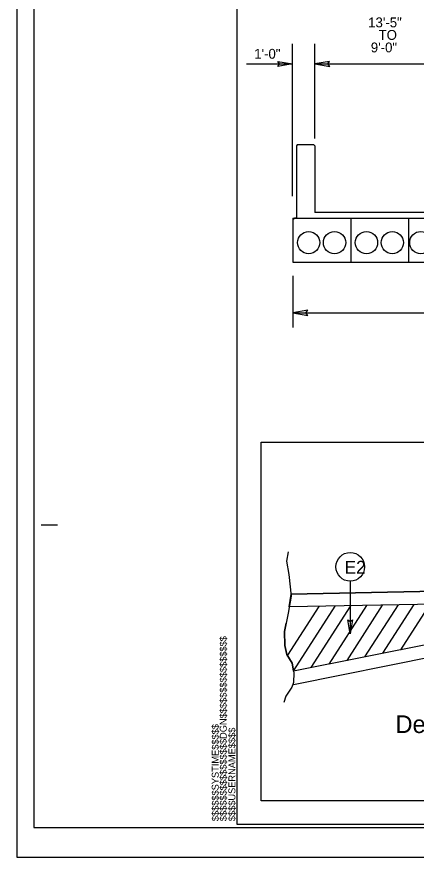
# Model space of a CAD drawing. Extents: x 1818040 to 1825768, y 638918 to 648046.
# Drawn here: x 1820393 to 1820696, y 645383 to 646022 of the extents above; entities that cross this region are included whole.
import ezdxf

# ---------------------------------------------------------------- set-up
doc = ezdxf.new("R2010")
doc.units = 0
for name, color, linetype in [('Default', 7, 'Continuous'), ('Old_Level_1', 7, 'Continuous'), ('Sheet Data Field CELL', 7, 'Continuous'), ('Sheet Plot Border Inside CELL', 7, 'Continuous'), ('Sheet Plot Border Outside CELL', 7, 'Continuous'), ('Sheet Typical CELL', 7, 'Continuous'), ('Typical Bridge Rail CELL', 7, 'Continuous'), ('Typical Detail Wedge2 CELL', 7, 'Continuous'), ('Typical ID Circle CELL', 7, 'Continuous'), ('Typical Terminator CELL', 7, 'Continuous'), ('Typical Text General CELL', 7, 'Continuous'), ('Typical Text ID Circle CELL', 7, 'Continuous')]:
    doc.layers.add(name, color=color, linetype=linetype)

msp = doc.modelspace()

# ---------------------------------------------------------------- linework, layer by layer
at = {"layer": 'Default'}
for p, q in [((1820602.34, 645885.64), (1820602.34, 646001.32)), ((1820619.19, 645929.41), (1820619.19, 646001.32)), ((1820567.26, 645986.11), (1820602.34, 645986.11)), ((1820619.19, 645986.11), (1820714.57, 645986.11)), ((1820602.6, 645869), (1821170.98, 645869)), ((1820602.6, 645869), (1820602.6, 645835.41)), ((1820862.17, 645873.14), (1820619.19, 645873.14)), ((1820646.5, 645869), (1820646.5, 645835.41)), ((1820646.5, 645869), (1820646.5, 645835.41)), ((1820690.4, 645869), (1820690.4, 645835.41)), ((1820602.6, 645835.41), (1821170.98, 645835.41)), ((1820602.56, 645825.17), (1820602.56, 645785.89)), ((1820602.56, 645796.99), (1821170.98, 645796.99))]:
    msp.add_line(p, q, dxfattribs=at)
for centre in [(1820614.52, 645850.35), (1820634.15, 645850.35), (1820658.42, 645850.35), (1820678.05, 645850.35), (1820699.72, 645850.36)]:
    msp.add_circle(centre, 8.47, dxfattribs=at)
at = {"layer": 'Old_Level_1'}
msp.add_lwpolyline([(1820578.56, 645698.83), (1821137.94, 645698.83), (1821137.94, 645426.3), (1820578.56, 645426.3)], close=True, dxfattribs=at)
at = {"layer": 'Sheet Plot Border Inside CELL'}
msp.add_lwpolyline([(1822072.43, 646461.05), (1820405.93, 646461.05), (1820405.93, 645405.95), (1822072.43, 645405.95)], close=True, dxfattribs=at)
at = {"layer": 'Sheet Plot Border Outside CELL'}
msp.add_lwpolyline([(1822076.93, 646483.5), (1820392.93, 646483.5), (1820392.93, 645383.5), (1822076.93, 645383.5)], close=True, dxfattribs=at)
at = {"layer": 'Sheet Typical CELL'}
for p, q in [((1820392.93, 646483.5), (1820392.93, 645383.5)), ((1820411.43, 645636), (1820423.93, 645636)), ((1820559.93, 645408.5), (1820559.93, 645408.5)), ((1820559.93, 645408.5), (1820559.93, 645408.5)), ((1820559.93, 645408.5), (1820559.93, 645408.5)), ((1820559.93, 645408.5), (1820559.93, 645408.5)), ((1820559.93, 645408.5), (1820559.93, 645408.5)), ((1820559.93, 645408.5), (1820559.93, 645408.5)), ((1820392.93, 645383.5), (1822076.93, 645383.5))]:
    msp.add_line(p, q, dxfattribs=at)
msp.add_lwpolyline([(1822059.93, 646458.5), (1820559.93, 646458.5), (1820559.93, 645408.5), (1822059.93, 645408.5)], close=True, dxfattribs=at)
msp.add_lwpolyline([(1820597.43, 645408.5), (1820597.43, 645408.5)], dxfattribs=at)
at = {"layer": 'Typical Bridge Rail CELL'}
for p, q in [((1820605.86, 645924.62), (1820605.2, 645923.96)), ((1820605.2, 645923.96), (1820605.2, 645869)), ((1820618.46, 645924.62), (1820605.86, 645924.62)), ((1820619.19, 645923.89), (1820618.46, 645924.62)), ((1820619.19, 645923.89), (1820619.19, 645873.14)), ((1820603.9, 645869), (1820602.6, 645867.69)), ((1820605.2, 645869), (1820603.9, 645869)), ((1820602.6, 645867.69), (1820602.6, 645858.57))]:
    msp.add_line(p, q, dxfattribs=at)
at = {"layer": 'Typical Detail Wedge2 CELL'}
for p, q in [((1820598.9, 645615.52), (1820597.61, 645608.39)), ((1820597.61, 645608.39), (1820599.56, 645598.25)), ((1820599.56, 645598.25), (1820601.28, 645581.83)), ((1820844.66, 645588.25), (1820601.17, 645583.39)), ((1820601.17, 645583.39), (1820844.66, 645588.25)), ((1820601.28, 645581.83), (1820598.9, 645568.87)), ((1820599.78, 645573.6), (1820601.17, 645583.39)), ((1820823.31, 645578.07), (1820599.78, 645573.6)), ((1820823.31, 645578.07), (1820599.78, 645573.6)), ((1820634.27, 645574.29), (1820602.91, 645525.33)), ((1820646.3, 645574.53), (1820616.17, 645527.5)), ((1820658.33, 645574.77), (1820629.79, 645530.22)), ((1820670.36, 645575.01), (1820643.41, 645532.95)), ((1820682.39, 645575.25), (1820657.03, 645535.67)), ((1820694.42, 645575.5), (1820670.66, 645538.4)), ((1820706.45, 645575.74), (1820684.28, 645541.12)), ((1820598.9, 645568.87), (1820596.1, 645554.83)), ((1820622.24, 645574.05), (1820598.43, 645536.89)), ((1820845.03, 645573.28), (1820603, 645524.86)), ((1820844.58, 645562.86), (1820602.92, 645514.52)), ((1820596.1, 645554.83), (1820596.32, 645544.24)), ((1820596.32, 645544.24), (1820598.05, 645537.56)), ((1820598.05, 645537.56), (1820601.94, 645530.85)), ((1820601.94, 645530.85), (1820603.23, 645523.51)), ((1820603.23, 645523.51), (1820603.01, 645516.17)), ((1820601.72, 645512.71), (1820597.19, 645505.79)), ((1820603.01, 645516.17), (1820601.72, 645512.71)), ((1820597.19, 645505.79), (1820595.67, 645501.04))]:
    msp.add_line(p, q, dxfattribs=at)
msp.add_lwpolyline([(1820602.99, 645524.86), (1820601.94, 645530.85), (1820598.05, 645537.56), (1820596.32, 645544.24), (1820596.1, 645554.83), (1820597.4, 645561.34)], dxfattribs=at)
at = {"layer": 'Typical ID Circle CELL'}
msp.add_line((1820646.1, 645593.17), (1820646.1, 645553.2), dxfattribs=at)
msp.add_circle((1820646.09, 645604.05), 10.88, dxfattribs=at)
at = {"layer": 'Typical Terminator CELL'}
for points in [[(1820591.09, 645988.05), (1820602.34, 645986.11), (1820591.03, 645984.11), (1820592.46, 645986.11)], [(1820630.44, 645988.05), (1820619.19, 645986.11), (1820630.5, 645984.11), (1820629.06, 645986.11)], [(1820613.81, 645798.93), (1820602.56, 645796.99), (1820613.87, 645794.99), (1820612.44, 645796.99)], [(1820647.91, 645563.75), (1820646.1, 645553.2), (1820644.22, 645563.81), (1820646.1, 645562.46)], [(1820647.91, 645563.75), (1820646.1, 645553.2), (1820644.22, 645563.81), (1820646.1, 645562.46)]]:
    msp.add_lwpolyline(points, close=True, dxfattribs=at)

# ---------------------------------------------------------------- texts
at = {"layer": 'Sheet Data Field CELL'}
for s, p in [('13\'-5" ', (1820659.69, 646013.87)), ('TO ', (1820667.61, 646004.37)), ('9\'-0"', (1820661.7, 645994.86)), ('1\'-0"', (1820573.16, 645990.05))]:
    msp.add_text(s, height=7.5, dxfattribs=at).set_placement(p)
at = {"layer": 'Sheet Typical CELL'}
for s, p in [('$$$$$$$$$$$$$$$$DGN$$$$$$$$$$$$$$$$', (1820552.28, 645410.86)), ('$$$$$$SYSTIME$$$$$', (1820546.23, 645410.86)), ('$$$$USERNAME$$$$', (1820558.86, 645410.87))]:
    msp.add_text(s, height=5.25, rotation=90, dxfattribs=at).set_placement(p)
at = {"layer": 'Typical Text General CELL'}
msp.add_text('Detail Showing Method of Wedging', height=13.4275, dxfattribs=at).set_placement((1820680.43, 645477.81))
at = {"layer": 'Typical Text ID Circle CELL'}
msp.add_text('E2', height=9.735, dxfattribs=at).set_placement((1820641.86, 645598.87))

doc.saveas('drawing.dxf')
